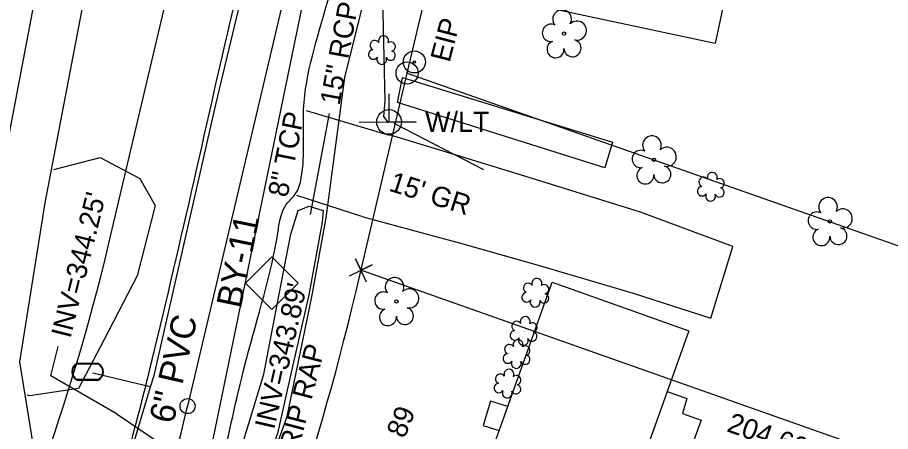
# Model space of a CAD drawing. Extents: x 2089016 to 2094354, y 862840 to 864725.
# Drawn here: x 2091434.2 to 2091607.8, y 863971.2 to 864053.4 of the extents above; entities that cross this region are included whole.
import ezdxf

# ---------------------------------------------------------------- set-up
doc = ezdxf.new("R2010")
doc.units = 0
for name, color, linetype in [('CTL Supplemental Horizontal and Vertical CELL', 7, 'Continuous'), ('CTL Supplemental Horizontal and Vertical Text', 7, 'Continuous'), ('Exist Building', 7, 'Continuous'), ('Exist Horizontal Alignment', 7, 'Continuous'), ('Exist Horizontal Alignment Station Label', 7, 'Continuous'), ('Exist Other Culture Area Outline', 7, 'Continuous'), ('Exist Other Culture Area Outline Text', 7, 'Continuous'), ('Exist Property Corner CELL', 7, 'Continuous'), ('Exist Property Iron Pin Text', 7, 'Continuous'), ('Exist Property Line', 7, 'Continuous'), ('Exist Property Line Text', 7, 'Continuous'), ('Exist Right of Way Line', 7, 'Continuous'), ('Exist Roads EOP', 7, 'Continuous'), ('Exist Roads Soil', 7, 'Continuous'), ('Exist Roads Soil Text', 7, 'Continuous'), ('Exist Structure Minor Pipes RCP 15 Inch', 7, 'Continuous'), ('Exist Structure Minor Pipes RCP 15 Inch Invert', 7, 'Continuous'), ('Exist Structure Minor Pipes RCP 15 Inch Leader', 7, 'Continuous'), ('Exist Structure Minor Pipes RCP 15 Inch Text', 7, 'Continuous'), ('Exist Utilities Gas UG Line SUE LOS B', 7, 'Continuous'), ('Exist Utilities Power Joint Use Telephone Text', 7, 'Continuous'), ('Exist Utilities Power UG Cable SUE LOS B', 7, 'Continuous'), ('Exist Utilities Sanitary Sewer UG Line', 7, 'Continuous'), ('Exist Utilities Sanitary Sewer UG Line Invert Elevation', 7, 'Continuous'), ('Exist Utilities Sanitary Sewer UG Line Text', 7, 'Continuous'), ('Exist Utilities Telephone UG Cable SUE LOS B', 7, 'Continuous'), ('Exist Utilities Water UG Line SUE LOS B', 7, 'Continuous'), ('Exist Utilities Water UG Line SUE LOS C', 7, 'Continuous'), ('Exist Utilities Water UG Line SUE LOS C Text', 7, 'Continuous'), ('Exist Vegetation Shrub CELL', 7, 'Continuous'), ('Exist Vegetation Tree CELL', 7, 'Continuous'), ('Exist Vegetation Woods Line', 7, 'Continuous'), ('Pattern 1', 7, 'Continuous'), ('Prop Conc Curb and Gutter', 7, 'Continuous'), ('Prop Drainage Structure Pipe RCP 36in Class IV', 7, 'Continuous'), ('Prop SS Fill Line', 7, 'Continuous')]:
    doc.layers.add(name, color=color, linetype=linetype)

msp = doc.modelspace()

# ---------------------------------------------------------------- linework, layer by layer
at = {"layer": 'CTL Supplemental Horizontal and Vertical CELL'}
msp.add_line((2091484.79, 864000.62), (2091484.79, 864000.62), dxfattribs=at)
msp.add_lwpolyline([(2091479.57, 864000.64), (2091484.81, 864005.88), (2091490.06, 864000.63), (2091484.82, 863995.39)], close=True, dxfattribs=at)
at = {"layer": 'Exist Building'}
for points in [[(2091580.7, 864084.72), (2091572.92, 864048.23), (2091540.88, 864055.07), (2091541.71, 864058.97), (2091539.54, 864059.42), (2091545.96, 864089.04), (2091547.98, 864088.61), (2091548.84, 864092.6), (2091550.75, 864092.19), (2091553.25, 864103.9), (2091571.23, 864100.04), (2091568.5, 864087.34)], [(2091567.71, 863991.16), (2091549.56, 863940.28), (2091522.37, 863949.98), (2091540.52, 864000.86)]]:
    msp.add_lwpolyline(points, close=True, dxfattribs=at)
at = {"layer": 'Exist Horizontal Alignment'}
msp.add_line((2091504.17, 864129.63), (2091468.04, 863976.22), dxfattribs=at)
msp.add_arc((2091098.16, 864063.33), 380, 321.5759, 346.748, dxfattribs=at)
at = {"layer": 'Exist Horizontal Alignment Station Label'}
msp.add_circle((2091468.04, 863976.22), 1.5, dxfattribs=at)
at = {"layer": 'Exist Other Culture Area Outline'}
for points in [[(2091473.13, 863949.53), (2091483.2, 863982.54), (2091486.28, 863998.43), (2091488.56, 864010.41), (2091490.05, 864015.08), (2091492.22, 864015.95), (2091494.97, 864015.1), (2091494.81, 864012.79), (2091492.13, 863998.34), (2091488.56, 863982.66), (2091485.94, 863970.77), (2091479.72, 863953.33), (2091477.79, 863947.66), (2091473.13, 863949.53)], [(2091563.4, 863979.09), (2091567.34, 863977.71), (2091566.44, 863974.77), (2091570.13, 863973.43), (2091564.66, 863958.37), (2091559.94, 863959.88), (2091557.5, 863952.2), (2091562.57, 863950.29), (2091560.78, 863944.47), (2091552.02, 863947.19)], [(2091531.71, 863976.15), (2091528.27, 863977.21), (2091526.79, 863972.39), (2091530.01, 863971.4)]]:
    msp.add_lwpolyline(points, dxfattribs=at)
at = {"layer": 'Exist Property Corner CELL'}
msp.add_line((2091502.5, 864003.2), (2091502.5, 864003.2), dxfattribs=at)
msp.add_lwpolyline([(2091500.25, 864002.12), (2091504.76, 864004.28), (2091502.5, 864003.2), (2091501.42, 864005.45), (2091503.58, 864000.94)], dxfattribs=at)
at = {"layer": 'Exist Property Line'}
for p, q in [((2091511.7, 864042.39), (2091854.39, 863921.86)), ((2091824.61, 863889.69), (2091502.5, 864003.2))]:
    msp.add_line(p, q, dxfattribs=at)
at = {"layer": 'Exist Right of Way Line'}
for p, q in [((2091452.8, 864010.25), (2091484.62, 864145.5)), ((2091511.7, 864042.39), (2091535.05, 864140.39)), ((2091501.47, 863998.8), (2091511.7, 864042.39))]:
    msp.add_line(p, q, dxfattribs=at)
for radius in [444.54, 494.54]:
    msp.add_arc((2091020.08, 864112.07), radius, 322.7135, 346.759, dxfattribs=at)
at = {"layer": 'Exist Roads EOP'}
for points in [[(2091441.1, 863921.91), (2091444.26, 863930.54), (2091451.5, 863951.02), (2091462.11, 863990.03), (2091470.34, 864025.4), (2091478.72, 864061.83), (2091488.18, 864099.79), (2091497.28, 864140.14), (2091508.39, 864182.61), (2091520.43, 864222.63), (2091532.13, 864263.12), (2091539.24, 864279.17)], [(2091458.4, 863915.67), (2091461.42, 863924.49), (2091469.42, 863944.94), (2091479.75, 863985.59), (2091486.04, 864011.02), (2091487.65, 864016.26), (2091489.53, 864018.43), (2091490.64, 864021.54), (2091491.12, 864028.71), (2091491.12, 864035.24), (2091495.79, 864056.26), (2091504.17, 864091.54), (2091506.21, 864096.08), (2091508.03, 864097.81), (2091509.43, 864104.3), (2091510.9, 864108.46), (2091509.69, 864112.64), (2091510.21, 864116.03), (2091515.22, 864135.56), (2091526.19, 864178.07), (2091537.83, 864216.97), (2091551.26, 864256.55)], [(2090159.86, 864177.45), (2090180.67, 864168.73), (2090222.86, 864151.65), (2090264.39, 864134.6), (2090306, 864117.79), (2090347.24, 864101.05), (2090392.99, 864082.57), (2090433.2, 864065.09), (2090472.83, 864048.96), (2090514.73, 864032.43), (2090559.97, 864014.05), (2090601.37, 863997.19), (2090646.29, 863978.82), (2090688.95, 863961.27), (2090733.38, 863942.96), (2090770.05, 863927.33), (2090814.52, 863908.72), (2090858.91, 863891), (2090901.15, 863874.17), (2090939.87, 863858.28), (2090962.72, 863848.64), (2090997.54, 863834.72), (2091036.07, 863819.08), (2091075.6, 863802.48), (2091112.88, 863787.77), (2091153.64, 863770.65), (2091194.67, 863753.49), (2091234.07, 863737.23), (2091276.57, 863719.33), (2091296.56, 863710.75), (2091332.88, 863695.67), (2091370.71, 863680.05), (2091411.45, 863662.85), (2091427.01, 863655.9), (2091440.19, 863646.8), (2091448.83, 863640.62), (2091463.67, 863633.85), (2091467.99, 863632.17), (2091469.11, 863631.07), (2091469.97, 863630.04), (2091470.37, 863629.28)]]:
    msp.add_spline(points, degree=3, dxfattribs=at)
at = {"layer": 'Exist Roads Soil'}
for p, q in [((2091491.61, 864034.93), (2091508.13, 864030.07)), ((2091502.68, 864013.87), (2091489.74, 864018.08))]:
    msp.add_line(p, q, dxfattribs=at)
for points in [[(2091485.82, 864199.68), (2091479.84, 864189.88), (2091466.83, 864148.87), (2091457.53, 864106.62), (2091449.87, 864069.96), (2091439.63, 864016.58), (2091434.62, 863984.99), (2091437.65, 863966.23)], [(2091459.37, 864174.96), (2091454.53, 864144.81), (2091448.34, 864108.66), (2091440.65, 864073.02), (2091430.46, 864019.64), (2091423.86, 863987.54), (2091421.76, 863972.64), (2091359.98, 863988.6), (2091336.21, 863998.07), (2091321.49, 863999.9), (2091315.08, 863979.88), (2091350.22, 863971), (2091390.3, 863962.86), (2091406.39, 863961.4), (2091417.61, 863959.47), (2091429.14, 863943.23)], [(2091502.68, 864013.87), (2091522.33, 864008.57), (2091537.77, 864004.24), (2091556.66, 863998.69), (2091572.06, 863993.67), (2091576.44, 864007.92), (2091558.08, 864014.76), (2091534.41, 864022.07), (2091517.31, 864027.32), (2091508.2, 864030.09)]]:
    msp.add_lwpolyline(points, dxfattribs=at)
at = {"layer": 'Exist Structure Minor Pipes RCP 15 Inch'}
for p, q in [((2091492.48, 864014.29), (2091496.23, 864034.38)), ((2091454.01, 863974.64), (2091477.9, 863958.52))]:
    msp.add_line(p, q, dxfattribs=at)
at = {"layer": 'Exist Structure Minor Pipes RCP 15 Inch Leader'}
msp.add_lwpolyline([(2091454.01, 863974.64), (2091440.87, 863982.26), (2091442.32, 863988.09)], dxfattribs=at)
at = {"layer": 'Exist Utilities Gas UG Line SUE LOS B'}
msp.add_lwpolyline([(2091438.29, 863868.65), (2091446.78, 863880.55), (2091469.49, 863926.78), (2091477.9, 863946.6), (2091487.83, 863974.17), (2091492.72, 863997.92), (2091495.61, 864013.62), (2091499.29, 864041.53), (2091509.34, 864081.8)], dxfattribs=at)
at = {"layer": 'Exist Utilities Power UG Cable SUE LOS B'}
msp.add_line((2091509.08, 864032.45), (2091526.87, 864023.2), dxfattribs=at)
at = {"layer": 'Exist Utilities Sanitary Sewer UG Line'}
msp.add_lwpolyline([(2091692.13, 864500.83), (2091501.01, 864105.51), (2091469.71, 863953.2), (2091320.59, 863732.95), (2090957.27, 863880.97), (2090681.31, 863994.88), (2090015.26, 864266.1)], dxfattribs=at)
at = {"layer": 'Exist Utilities Telephone UG Cable SUE LOS B'}
msp.add_lwpolyline([(2091507.97, 864032.52), (2091507.05, 864033.76), (2091507.35, 864036.85), (2091506.84, 864057.33), (2091513.07, 864080.92)], dxfattribs=at)
at = {"layer": 'Exist Utilities Water UG Line SUE LOS B'}
msp.add_line((2091449.19, 863982.83), (2091460.63, 863980.13), dxfattribs=at)
msp.add_lwpolyline([(2091455.27, 863961.79), (2091455.66, 863963.15), (2091456.23, 863965.17), (2091460.66, 863980.04), (2091461.38, 863982.3)], dxfattribs=at)
at = {"layer": 'Exist Utilities Water UG Line SUE LOS C'}
msp.add_lwpolyline([(2091461.38, 863982.3), (2091473.68, 864036.11), (2091489.51, 864102.28), (2091505.34, 864168.7), (2091522.33, 864224.48), (2091530.35, 864254.79), (2091550.39, 864300.93)], dxfattribs=at)
at = {"layer": 'Exist Vegetation Shrub CELL'}
for p, q in [((2091506.77, 864046.78), (2091506.77, 864046.78)), ((2091572.16, 864019.62), (2091572.16, 864019.62)), ((2091537.27, 863998.56), (2091537.27, 863998.56)), ((2091534.94, 863990.97), (2091534.94, 863990.97)), ((2091533.53, 863986.38), (2091533.53, 863986.38)), ((2091531.72, 863980.5), (2091531.72, 863980.5))]:
    msp.add_line(p, q, dxfattribs=at)
for centre, radius, start, end in [((2091507, 864048.82), 0.99, 334.8391, 200.4717), ((2091505.29, 864047.91), 0.968, 35.8908, 245.4216), ((2091508.44, 864047.65), 0.929, 284.4567, 126.0861), ((2091504.97, 864046.08), 0.955, 95.1099, 327.9534), ((2091508.41, 864045.85), 0.937, 204.9913, 73.4601), ((2091506.64, 864045.1), 0.984, 151.2797, 21.387), ((2091572.39, 864021.66), 0.99, 334.8391, 200.4717), ((2091570.68, 864020.75), 0.968, 35.8908, 245.4216), ((2091573.84, 864020.49), 0.929, 284.4567, 126.0861), ((2091570.36, 864018.92), 0.955, 95.1099, 327.9534), ((2091572.04, 864017.94), 0.984, 151.2797, 21.387), ((2091573.8, 864018.69), 0.937, 204.9913, 73.4601), ((2091537.5, 864000.6), 0.99, 334.8391, 200.4717), ((2091535.79, 863999.68), 0.968, 35.8908, 245.4216), ((2091538.94, 863999.42), 0.929, 284.4567, 126.0861), ((2091535.47, 863997.85), 0.955, 95.1099, 327.9534), ((2091538.91, 863997.63), 0.937, 204.9913, 73.4601), ((2091537.14, 863996.87), 0.984, 151.2797, 21.387), ((2091535.17, 863993.01), 0.99, 334.8391, 200.4717), ((2091533.46, 863992.1), 0.968, 35.8908, 245.4216), ((2091536.61, 863991.84), 0.929, 284.4567, 126.0861), ((2091533.14, 863990.27), 0.955, 95.1099, 327.9534), ((2091536.58, 863990.04), 0.937, 204.9913, 73.4601), ((2091533.76, 863988.42), 0.99, 334.8391, 200.4717), ((2091534.81, 863989.29), 0.984, 151.2797, 21.387), ((2091532.05, 863987.51), 0.968, 35.8908, 245.4216), ((2091535.2, 863987.25), 0.929, 284.4567, 126.0861), ((2091531.73, 863985.68), 0.955, 95.1099, 327.9534), ((2091535.17, 863985.45), 0.937, 204.9913, 73.4601), ((2091531.95, 863982.54), 0.99, 334.8391, 200.4717), ((2091533.4, 863984.7), 0.984, 151.2797, 21.387), ((2091530.24, 863981.63), 0.968, 35.8908, 245.4216), ((2091533.4, 863981.37), 0.929, 284.4567, 126.0861), ((2091529.92, 863979.8), 0.955, 95.1099, 327.9534), ((2091533.36, 863979.57), 0.937, 204.9913, 73.4601), ((2091531.6, 863978.82), 0.984, 151.2797, 21.387)]:
    msp.add_arc(centre, radius, start, end, dxfattribs=at)
at = {"layer": 'Exist Vegetation Tree CELL'}
for p, q in [((2091542.91, 864050.23), (2091542.91, 864050.23)), ((2091560.77, 864025.16), (2091560.77, 864025.16)), ((2091595.77, 864012.91), (2091595.77, 864012.91)), ((2091509.58, 863997.02), (2091509.58, 863997.02))]:
    msp.add_line(p, q, dxfattribs=at)
for centre in [(2091542.91, 864050.23), (2091560.77, 864025.16), (2091595.77, 864012.91), (2091509.58, 863997.02)]:
    msp.add_circle(centre, 0.326, dxfattribs=at)
for centre, radius, start, end in [((2091542.52, 864053.1), 1.86, 330.1651, 219.7134), ((2091540.3, 864050.38), 1.73, 62.6636, 279.3457), ((2091545.46, 864050.82), 1.9, 257.1011, 134.1999), ((2091541.2, 864047.11), 1.69, 111.5671, 6.231), ((2091544.58, 864047.33), 1.7, 181.2822, 74.56), ((2091560.38, 864028.04), 1.86, 330.1651, 219.7134), ((2091558.16, 864025.32), 1.73, 62.6636, 279.3457), ((2091563.32, 864025.75), 1.9, 257.1011, 134.1999), ((2091559.06, 864022.04), 1.69, 111.5671, 6.231), ((2091562.44, 864022.26), 1.7, 181.2822, 74.56), ((2091595.39, 864015.79), 1.86, 330.1651, 219.7134), ((2091593.17, 864013.07), 1.73, 62.6636, 279.3457), ((2091598.32, 864013.5), 1.9, 257.1011, 134.1999), ((2091594.07, 864009.79), 1.69, 111.5671, 6.231), ((2091597.45, 864010.01), 1.7, 181.2822, 74.56), ((2091509.2, 863999.9), 1.86, 330.1651, 219.7134), ((2091512.13, 863997.61), 1.9, 257.1011, 134.1999), ((2091506.98, 863997.18), 1.73, 62.6636, 279.3457), ((2091511.25, 863994.12), 1.7, 181.2822, 74.56), ((2091507.88, 863993.9), 1.69, 111.5671, 6.231)]:
    msp.add_arc(centre, radius, start, end, dxfattribs=at)
at = {"layer": 'Exist Vegetation Woods Line'}
for points in [[(2091510.78, 864041.48), (2091552.56, 864028.64), (2091550.99, 864023.56), (2091509.8, 864036.51), (2091510.78, 864041.48)], [(2091441.45, 864023.26), (2091450.67, 864025.59), (2091458.57, 864021.42), (2091461.62, 864016.07)], [(2091461.62, 864016.07), (2091457.99, 864002.13), (2091451.46, 863989.44), (2091446.32, 863979.69), (2091436.65, 863978.26), (2091436.15, 863978.41)]]:
    msp.add_lwpolyline(points, dxfattribs=at)
at = {"layer": 'Pattern 1'}
msp.add_line((2091448.17, 863983.04), (2091448.17, 863983.04), dxfattribs=at)
for points in [[(2091446.13, 863984.74), (2091450.21, 863984.74)], [(2091446.13, 863984.61), (2091450.21, 863984.61)], [(2091450.21, 863981.48), (2091446.11, 863981.48)], [(2091450.21, 863981.34), (2091446.11, 863981.34)]]:
    msp.add_lwpolyline(points, dxfattribs=at)
for centre, radius, start, end in [((2091446.86, 863983.04), 1.86, 113.178, 245.9794), ((2091446.88, 863983.04), 1.73, 115.3009, 243.7824), ((2091449.46, 863983.04), 1.86, 293.6483, 66.3084), ((2091449.48, 863983.04), 1.73, 295.1272, 64.8728)]:
    msp.add_arc(centre, radius, start, end, dxfattribs=at)
at = {"layer": 'Prop Conc Curb and Gutter'}
for radius in [2.2, 0.0707]:
    msp.add_circle((2091511.7, 864042.39), radius, dxfattribs=at)
at = {"layer": 'Prop Drainage Structure Pipe RCP 36in Class IV'}
for radius in [2.18, 0.24]:
    msp.add_circle((2091513.14, 864044.6), radius, dxfattribs=at)
at = {"layer": 'Prop SS Fill Line'}
msp.add_line((2091508.1, 864032.67), (2091508.1, 864032.67), dxfattribs=at)
msp.add_lwpolyline([(2091502.16, 864032.67), (2091513.5, 864032.63), (2091508.1, 864032.65), (2091508.1, 864038.29)], dxfattribs=at)
msp.add_circle((2091508.1, 864032.67), 2.45, dxfattribs=at)

# ---------------------------------------------------------------- texts
at = {"layer": 'CTL Supplemental Horizontal and Vertical Text'}
msp.add_text('BY-11', height=5, rotation=78.3839, dxfattribs=at).set_placement((2091478.62, 863995.46))
at = {"layer": 'Exist Other Culture Area Outline Text'}
msp.add_text('RIP RAP', height=4, rotation=75.4473, dxfattribs=at).set_placement((2091490.05, 863967.22))
at = {"layer": 'Exist Property Iron Pin Text'}
msp.add_text('EIP', height=4, rotation=75.3785, dxfattribs=at).set_placement((2091520.13, 864044.34))
at = {"layer": 'Exist Property Line Text'}
msp.add_text("204.60'", height=4, rotation=340.5887, dxfattribs=at).set_placement((2091575.07, 863971.26))
at = {"layer": 'Exist Roads Soil Text'}
msp.add_text("15' GR", height=4, rotation=342.4462, dxfattribs=at).set_placement((2091507.88, 864019.06))
at = {"layer": 'Exist Structure Minor Pipes RCP 15 Inch Invert'}
for s, rotation, p in [("INV=344.25'", 76.0479, (2091444.74, 863989.54)), ("INV=343.89'", 77.0629, (2091485.25, 863971.42))]:
    msp.add_text(s, height=4, rotation=rotation, dxfattribs=at).set_placement(p)
at = {"layer": 'Exist Structure Minor Pipes RCP 15 Inch Text'}
msp.add_text('15" RCP', height=4, rotation=79.4132, dxfattribs=at).set_placement((2091498.25, 864035.85))
at = {"layer": 'Exist Utilities Power Joint Use Telephone Text'}
msp.add_text('W/LT', height=4, dxfattribs=at).set_placement((2091515.28, 864030.7))
at = {"layer": 'Exist Utilities Sanitary Sewer UG Line Invert Elevation'}
msp.add_text('INV=341.89', height=4, rotation=67.5689, dxfattribs=at).set_placement((2091502.59, 863948.87))
at = {"layer": 'Exist Utilities Sanitary Sewer UG Line Text'}
msp.add_text('8" TCP', height=4, rotation=78.387, dxfattribs=at).set_placement((2091487.88, 864017.53))
at = {"layer": 'Exist Utilities Water UG Line SUE LOS C Text'}
msp.add_text('6" PVC', height=5, rotation=77.1213, dxfattribs=at).set_placement((2091465.22, 863972.54))

doc.saveas('drawing.dxf')
